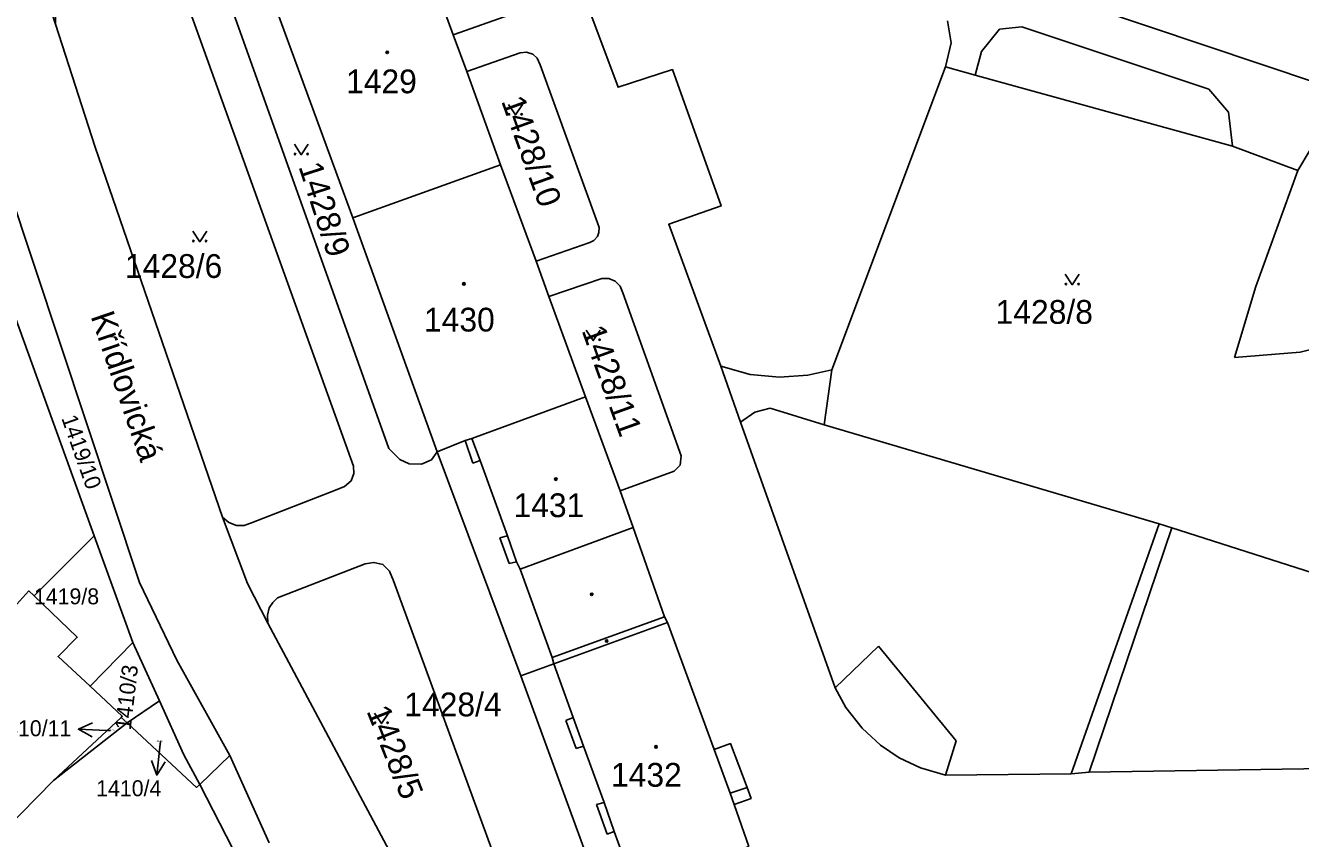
# Model space of a CAD drawing. Extents: x -598934 to -598196, y -1162208 to -1161502.
# Drawn here: x -598686.2 to -598595, y -1161698.2 to -1161640.1 of the extents above; entities that cross this region are included whole.
import ezdxf

# ---------------------------------------------------------------- set-up
doc = ezdxf.new("R2010")
doc.units = 0
for name, color, linetype in [('KN_CAR_KR', 7, 'Continuous'), ('KN_KULTURY', 7, 'Continuous'), ('KN_PARC_CIS_POM', 7, 'Continuous'), ('KN_PARC_CIS_POZ', 7, 'Continuous'), ('KN_PARC_CIS_STAV', 7, 'Continuous'), ('KN_PARC_PLOCHA', 7, 'Continuous'), ('KN_ULICE', 7, 'Continuous'), ('PARC_C_SIPKA', 7, 'Continuous'), ('parcely_l', 7, 'Continuous')]:
    doc.layers.add(name, color=color, linetype=linetype)

msp = doc.modelspace()

# ---------------------------------------------------------------- linework, layer by layer
at = {"layer": 'KN_CAR_KR'}
for points in [[(-598609.95, -1161638.83), (-598593.83, -1161644.24)], [(-598620.01, -1161641.36), (-598620.28, -1161639.8)], [(-598614.96, -1161640.21), (-598616.57, -1161640.38)], [(-598614.96, -1161640.21), (-598601.59, -1161644.68)], [(-598617.85, -1161641.98), (-598616.57, -1161640.38)], [(-598620.01, -1161641.36), (-598620.42, -1161643.09)], [(-598617.85, -1161641.98), (-598618.3, -1161643.68)], [(-598628.55, -1161664.74), (-598620.42, -1161643.09)], [(-598620.42, -1161643.09), (-598618.3, -1161643.68)], [(-598618.3, -1161643.68), (-598599.9, -1161648.76)], [(-598601.59, -1161644.68), (-598600.19, -1161646.33)], [(-598599.9, -1161648.76), (-598600.19, -1161646.33)], [(-598599.9, -1161648.76), (-598595.24, -1161650.49)], [(-598595.24, -1161650.49), (-598594.36, -1161649.02)], [(-598598.24, -1161658.79), (-598595.24, -1161650.49)], [(-598599.77, -1161663.85), (-598598.24, -1161658.79)], [(-598587.65, -1161661.6), (-598595.08, -1161663.48)], [(-598595.08, -1161663.48), (-598599.77, -1161663.85)], [(-598636.49, -1161664.47), (-598634.38, -1161665.08)], [(-598630.27, -1161665.13), (-598628.55, -1161664.74)], [(-598629.1, -1161668.66), (-598628.55, -1161664.74)], [(-598634.38, -1161665.08), (-598632.3, -1161665.26)], [(-598632.3, -1161665.26), (-598630.27, -1161665.13)], [(-598632.96, -1161667.48), (-598634.05, -1161667.76)], [(-598629.1, -1161668.66), (-598632.96, -1161667.48)], [(-598634.05, -1161667.76), (-598635.07, -1161668.48)], [(-598605.16, -1161675.75), (-598629.1, -1161668.66)], [(-598654.21, -1161671.41), (-598654.77, -1161669.8)], [(-598653.69, -1161671.22), (-598654.29, -1161669.64)], [(-598653.69, -1161671.22), (-598654.21, -1161671.41)], [(-598651.74, -1161676.61), (-598653.69, -1161671.22)], [(-598605.16, -1161675.75), (-598611.45, -1161693.61)], [(-598604.25, -1161676.04), (-598605.16, -1161675.75)], [(-598652.27, -1161676.75), (-598651.74, -1161676.61)], [(-598651.74, -1161676.61), (-598651.1, -1161678.47)], [(-598650.83, -1161678.98), (-598642.76, -1161676.01)], [(-598604.25, -1161676.04), (-598610.15, -1161693.51)], [(-598579.9, -1161683.83), (-598604.25, -1161676.04)], [(-598651.62, -1161678.59), (-598652.27, -1161676.75)], [(-598651.1, -1161678.47), (-598651.62, -1161678.59)], [(-598650.83, -1161678.98), (-598651.1, -1161678.47)], [(-598648.55, -1161685.29), (-598650.83, -1161678.98)], [(-598640.5, -1161682.4), (-598648.55, -1161685.29)], [(-598628.32, -1161687.47), (-598625.22, -1161684.5)], [(-598625.22, -1161684.5), (-598619.67, -1161691.25)], [(-598648.42, -1161685.75), (-598648.55, -1161685.29)], [(-598647.03, -1161689.59), (-598648.42, -1161685.75)], [(-598647.57, -1161689.8), (-598647.03, -1161689.59)], [(-598646.83, -1161691.81), (-598647.57, -1161689.8)], [(-598646.31, -1161691.64), (-598647.03, -1161689.59)], [(-598619.67, -1161691.25), (-598620.43, -1161693.71)], [(-598646.31, -1161691.64), (-598646.83, -1161691.81)], [(-598644.82, -1161695.66), (-598646.31, -1161691.64)], [(-598636.95, -1161691.89), (-598635.81, -1161695)], [(-598671.58, -1161692.3), (-598668.78, -1161698.56)], [(-598634.61, -1161694.6), (-598635.81, -1161695)], [(-598645.37, -1161695.82), (-598644.82, -1161695.66)], [(-598644.6, -1161697.92), (-598645.37, -1161695.82)], [(-598644.1, -1161697.73), (-598644.82, -1161695.66)], [(-598635.81, -1161695), (-598635.53, -1161695.8)], [(-598644.1, -1161697.73), (-598644.6, -1161697.92)], [(-598642.64, -1161701.79), (-598644.1, -1161697.73)]]:
    msp.add_lwpolyline(points, dxfattribs=at)
at = {"layer": 'KN_KULTURY'}
for points in [[(-598651.672, -1161645.772), (-598651.172, -1161646.522), (-598650.672, -1161645.772)], [(-598666.972, -1161648.612), (-598666.472, -1161649.362), (-598665.972, -1161648.612)], [(-598674.232, -1161654.832), (-598673.732, -1161655.582), (-598673.232, -1161654.832)], [(-598611.862, -1161657.912), (-598611.362, -1161658.662), (-598610.862, -1161657.912)], [(-598646.102, -1161661.892), (-598645.602, -1161662.642), (-598645.102, -1161661.892)], [(-598661.252, -1161689.272), (-598660.752, -1161690.022), (-598660.252, -1161689.272)]]:
    msp.add_lwpolyline(points, dxfattribs=at)
for centre, radius in [((-598660.33, -1161642.04), 0.09), ((-598660.33, -1161642.04), 0.0398), ((-598651.622, -1161646.471), 0.05), ((-598650.723, -1161646.471), 0.05), ((-598666.922, -1161649.311), 0.05), ((-598666.023, -1161649.311), 0.05), ((-598674.182, -1161655.531), 0.05), ((-598673.283, -1161655.531), 0.05), ((-598654.85, -1161658.59), 0.09), ((-598654.85, -1161658.59), 0.0398), ((-598611.812, -1161658.611), 0.05), ((-598610.913, -1161658.611), 0.05), ((-598646.052, -1161662.591), 0.05), ((-598645.153, -1161662.591), 0.05), ((-598648.28, -1161672.55), 0.09), ((-598648.28, -1161672.55), 0.0398), ((-598645.71, -1161680.79), 0.09), ((-598645.71, -1161680.79), 0.0398), ((-598644.64, -1161684.12), 0.09), ((-598644.64, -1161684.12), 0.0398), ((-598661.202, -1161689.971), 0.05), ((-598660.303, -1161689.971), 0.05), ((-598641.12, -1161691.69), 0.09), ((-598641.12, -1161691.69), 0.0398)]:
    msp.add_circle(centre, radius, dxfattribs=at)
at = {"layer": 'KN_PARC_PLOCHA'}
for points in [[(-598686.46, -1161632.58), (-598684.05, -1161640.04), (-598681.2, -1161648.82), (-598672.1, -1161675.27), (-598670.33, -1161680.01), (-598668.86, -1161682.84), (-598656.62, -1161705.79), (-598649.12, -1161714.49), (-598643.96, -1161720.2), (-598630.79, -1161735.6), (-598615.08, -1161754.64), (-598621.01, -1161760.25)], [(-598648.15, -1161632.92), (-598643.83, -1161644.54), (-598639.95, -1161643.28), (-598636.46, -1161653.02), (-598640.21, -1161654.33), (-598636.49, -1161664.47), (-598635.07, -1161668.48), (-598628.32, -1161687.47), (-598627.54, -1161688.87), (-598626.39, -1161690.35), (-598625.07, -1161691.56), (-598623.73, -1161692.47), (-598622.2, -1161693.2), (-598620.43, -1161693.71), (-598611.45, -1161693.61), (-598610.15, -1161693.51), (-598593.28, -1161693.23)], [(-598593.28, -1161693.23), (-598610.15, -1161693.51), (-598611.45, -1161693.61), (-598620.43, -1161693.71), (-598622.2, -1161693.2), (-598623.73, -1161692.47), (-598625.07, -1161691.56), (-598626.39, -1161690.35), (-598627.54, -1161688.87), (-598628.32, -1161687.47), (-598635.07, -1161668.48), (-598636.49, -1161664.47), (-598640.21, -1161654.33), (-598636.46, -1161653.02), (-598639.95, -1161643.28), (-598643.83, -1161644.54), (-598648.15, -1161632.92)], [(-598651.9, -1161639.47), (-598655.61, -1161640.79), (-598658.24, -1161633.59)], [(-598648.85, -1161709.97), (-598659.88, -1161679.81), (-598660.16, -1161679.12), (-598660.64, -1161678.65), (-598661.28, -1161678.5), (-598661.92, -1161678.6), (-598668.17, -1161681.04), (-598668.52, -1161681.36), (-598668.76, -1161681.75), (-598668.89, -1161682.28), (-598668.86, -1161682.84), (-598670.33, -1161680.01), (-598672.1, -1161675.27), (-598671.66, -1161675.65), (-598671.11, -1161675.86), (-598670.57, -1161675.86), (-598670.03, -1161675.68), (-598664.03, -1161673.35), (-598663.39, -1161673.09), (-598662.9, -1161672.67), (-598662.72, -1161672.16), (-598662.74, -1161671.63), (-598675.31, -1161636.67)], [(-598668.84, -1161637.36), (-598662.79, -1161653.87), (-598656.76, -1161670.59), (-598657.17, -1161671.17), (-598657.87, -1161671.49), (-598658.76, -1161671.46), (-598659.44, -1161671.16), (-598660.21, -1161670.37), (-598671.33, -1161639.25)], [(-598671.33, -1161639.25), (-598660.21, -1161670.37), (-598659.44, -1161671.16), (-598658.76, -1161671.46), (-598657.87, -1161671.49), (-598657.17, -1161671.17), (-598656.76, -1161670.59), (-598650.79, -1161686.62), (-598644.94, -1161702.57)], [(-598634.49, -1161698.82), (-598635.53, -1161695.8), (-598634.32, -1161695.37), (-598634.61, -1161694.6), (-598635.8, -1161691.46), (-598636.95, -1161691.89), (-598640.3, -1161682.8), (-598640.5, -1161682.4), (-598642.76, -1161676.01), (-598643.67, -1161673.38), (-598639.82, -1161671.99), (-598639.4, -1161671.56), (-598639.31, -1161670.88), (-598643.5, -1161659.24), (-598643.69, -1161658.75), (-598644.03, -1161658.39), (-598644.48, -1161658.21), (-598644.99, -1161658.22), (-598648.77, -1161659.49), (-598649.69, -1161656.97), (-598645.84, -1161655.64), (-598645.56, -1161655.49), (-598645.31, -1161655.21), (-598645.2, -1161654.92), (-598645.19, -1161654.57), (-598645.3, -1161654.24), (-598649.4, -1161642.93), (-598649.61, -1161642.46), (-598649.92, -1161642.17), (-598650.37, -1161642.03), (-598650.84, -1161642.09), (-598654.65, -1161643.41), (-598655.61, -1161640.79), (-598651.9, -1161639.47)], [(-598623.69, -1161762.79), (-598630.21, -1161755.2), (-598643.12, -1161738.93), (-598643.44, -1161738.54), (-598646.87, -1161734.51), (-598646.1, -1161732.88), (-598663.98, -1161712.27), (-598668.05, -1161705.44), (-598673.72, -1161694.38), (-598671.58, -1161692.3), (-598675.38, -1161685.5), (-598678.03, -1161679.94), (-598687.48, -1161651.51)], [(-598687.25, -1161681.97), (-598685.95, -1161680.54), (-598685.58, -1161680.89), (-598682.49, -1161683.85), (-598683.86, -1161685.23), (-598681.57, -1161687.36), (-598679.27, -1161689.5), (-598679.36, -1161689.58), (-598684.2, -1161694.1), (-598703.13, -1161713.4)], [(-598703.13, -1161713.4), (-598684.2, -1161694.1), (-598678.92, -1161689.98), (-598673.96, -1161694.59), (-598673.72, -1161694.38), (-598668.05, -1161705.44), (-598663.98, -1161712.27), (-598661.59, -1161716.28), (-598659.05, -1161719.64), (-598655.51, -1161724.33), (-598649.66, -1161731.23), (-598647.28, -1161734.03), (-598646.87, -1161734.51), (-598643.44, -1161738.54), (-598643.12, -1161738.93), (-598630.21, -1161755.2), (-598631.23, -1161754.62), (-598632.35, -1161754.49), (-598633.32, -1161754.79), (-598634.09, -1161755.38), (-598639.5, -1161760.37)]]:
    msp.add_lwpolyline(points, dxfattribs=at)
for points in [[(-598655.61, -1161640.79), (-598654.65, -1161643.41), (-598652.24, -1161650.08), (-598662.79, -1161653.87), (-598668.84, -1161637.36), (-598658.24, -1161633.59)], [(-598672.1, -1161675.27), (-598681.2, -1161648.82), (-598684.05, -1161640.04), (-598684.05, -1161639.16), (-598683.81, -1161638.35), (-598683.25, -1161637.58), (-598682.43, -1161637.05), (-598677.11, -1161635.02), (-598676.56, -1161635.06), (-598676.08, -1161635.26), (-598675.59, -1161635.87), (-598675.31, -1161636.67), (-598662.74, -1161671.63), (-598662.72, -1161672.16), (-598662.9, -1161672.67), (-598663.39, -1161673.09), (-598664.03, -1161673.35), (-598670.03, -1161675.68), (-598670.57, -1161675.86), (-598671.11, -1161675.86), (-598671.66, -1161675.65)], [(-598649.69, -1161656.97), (-598652.24, -1161650.08), (-598654.65, -1161643.41), (-598650.84, -1161642.09), (-598650.37, -1161642.03), (-598649.92, -1161642.17), (-598649.61, -1161642.46), (-598649.4, -1161642.93), (-598645.3, -1161654.24), (-598645.19, -1161654.57), (-598645.2, -1161654.92), (-598645.31, -1161655.21), (-598645.56, -1161655.49), (-598645.84, -1161655.64)], [(-598649.69, -1161656.97), (-598648.77, -1161659.49), (-598646.16, -1161666.68), (-598654.29, -1161669.64), (-598654.77, -1161669.8), (-598656.76, -1161670.59), (-598662.79, -1161653.87), (-598652.24, -1161650.08)], [(-598681.27, -1161676.6), (-598685.58, -1161680.89), (-598685.95, -1161680.54), (-598687.25, -1161681.97), (-598689.63, -1161679.64), (-598687.53, -1161677.48), (-598692.75, -1161672.48), (-598690.15, -1161669.88), (-598695.26, -1161664.81), (-598692.73, -1161662.19), (-598698.04, -1161657.01), (-598693.48, -1161653.2), (-598691.2, -1161650.93), (-598690.66, -1161650.66), (-598690.42, -1161651.33)], [(-598673.72, -1161694.38), (-598674.87, -1161692.27), (-598676.62, -1161688.4), (-598678.51, -1161684.23), (-598681.27, -1161676.6), (-598690.42, -1161651.33), (-598690.66, -1161650.66), (-598690.08, -1161650.46), (-598689.38, -1161650.41), (-598688.63, -1161650.59), (-598687.98, -1161650.98), (-598687.48, -1161651.51), (-598678.03, -1161679.94), (-598675.38, -1161685.5), (-598671.58, -1161692.3)], [(-598643.67, -1161673.38), (-598646.16, -1161666.68), (-598648.77, -1161659.49), (-598644.99, -1161658.22), (-598644.48, -1161658.21), (-598644.03, -1161658.39), (-598643.69, -1161658.75), (-598643.5, -1161659.24), (-598639.31, -1161670.88), (-598639.4, -1161671.56), (-598639.82, -1161671.99)], [(-598643.67, -1161673.38), (-598642.76, -1161676.01), (-598640.5, -1161682.4), (-598640.3, -1161682.8), (-598648.42, -1161685.75), (-598650.79, -1161686.62), (-598656.76, -1161670.59), (-598654.77, -1161669.8), (-598654.29, -1161669.64), (-598646.16, -1161666.68)], [(-598678.51, -1161684.23), (-598681.57, -1161687.36), (-598683.86, -1161685.23), (-598682.49, -1161683.85), (-598685.58, -1161680.89), (-598681.27, -1161676.6)], [(-598649.12, -1161714.49), (-598656.62, -1161705.79), (-598668.86, -1161682.84), (-598668.89, -1161682.28), (-598668.76, -1161681.75), (-598668.52, -1161681.36), (-598668.17, -1161681.04), (-598661.92, -1161678.6), (-598661.28, -1161678.5), (-598660.64, -1161678.65), (-598660.16, -1161679.12), (-598659.88, -1161679.81), (-598648.85, -1161709.97), (-598647.75, -1161713.25)], [(-598634.49, -1161698.82), (-598642.64, -1161701.79), (-598644.94, -1161702.57), (-598650.79, -1161686.62), (-598648.42, -1161685.75), (-598640.3, -1161682.8), (-598636.95, -1161691.89), (-598635.8, -1161691.46), (-598634.61, -1161694.6), (-598634.32, -1161695.37), (-598635.53, -1161695.8)], [(-598676.62, -1161688.4), (-598678.92, -1161689.98), (-598679.36, -1161689.58), (-598679.27, -1161689.5), (-598681.57, -1161687.36), (-598678.51, -1161684.23)], [(-598673.72, -1161694.38), (-598673.96, -1161694.59), (-598678.92, -1161689.98), (-598676.62, -1161688.4), (-598674.87, -1161692.27)], [(-598678.92, -1161689.98), (-598684.2, -1161694.1), (-598679.36, -1161689.58)]]:
    msp.add_lwpolyline(points, close=True, dxfattribs=at)
at = {"layer": 'PARC_C_SIPKA'}
for points in [[(-598681.428, -1161690.973), (-598682.409, -1161690.436), (-598681.391, -1161689.973)], [(-598680.12, -1161690.52), (-598680.4, -1161690.51), (-598682.409, -1161690.436)], [(-598676.53, -1161691.31), (-598676.58, -1161691.71), (-598676.808, -1161693.707)], [(-598676.198, -1161692.77), (-598676.808, -1161693.707), (-598677.191, -1161692.657)]]:
    msp.add_lwpolyline(points, dxfattribs=at)
at = {"layer": 'parcely_l'}
for points in [[(-598656.76, -1161670.59), (-598657.17, -1161671.17), (-598657.87, -1161671.49), (-598658.76, -1161671.46), (-598659.44, -1161671.16), (-598660.21, -1161670.37), (-598671.33, -1161639.25), (-598672.4, -1161636.02), (-598672.19, -1161635.03), (-598671.8, -1161634.41), (-598671.22, -1161633.94), (-598663.77, -1161631.3), (-598661.92, -1161630.82), (-598660.03, -1161630.71), (-598658.06, -1161631), (-598656.16, -1161631.68), (-598653.82, -1161633.91), (-598651.31, -1161637.82), (-598651.19, -1161638.33), (-598651.3, -1161638.86), (-598651.55, -1161639.21), (-598651.9, -1161639.47), (-598655.61, -1161640.79)], [(-598593.28, -1161693.23), (-598610.15, -1161693.51), (-598611.45, -1161693.61), (-598620.43, -1161693.71), (-598622.2, -1161693.2), (-598623.73, -1161692.47), (-598625.07, -1161691.56), (-598626.39, -1161690.35), (-598627.54, -1161688.87), (-598628.32, -1161687.47), (-598635.07, -1161668.48), (-598636.49, -1161664.47), (-598640.21, -1161654.33), (-598636.46, -1161653.02), (-598639.95, -1161643.28), (-598643.83, -1161644.54), (-598648.15, -1161632.92)], [(-598655.61, -1161640.79), (-598658.24, -1161633.59), (-598668.84, -1161637.36), (-598662.79, -1161653.87)], [(-598684.05, -1161640.04), (-598684.05, -1161639.16), (-598683.81, -1161638.35), (-598683.25, -1161637.58), (-598682.43, -1161637.05), (-598677.11, -1161635.02), (-598676.56, -1161635.06), (-598676.08, -1161635.26), (-598675.59, -1161635.87), (-598675.31, -1161636.67), (-598662.74, -1161671.63), (-598662.72, -1161672.16), (-598662.9, -1161672.67), (-598663.39, -1161673.09), (-598664.03, -1161673.35), (-598670.03, -1161675.68), (-598670.57, -1161675.86), (-598671.11, -1161675.86), (-598671.66, -1161675.65), (-598672.1, -1161675.27)], [(-598684.05, -1161640.04), (-598681.2, -1161648.82), (-598672.1, -1161675.27)], [(-598654.65, -1161643.41), (-598655.61, -1161640.79)], [(-598654.65, -1161643.41), (-598650.84, -1161642.09), (-598650.37, -1161642.03), (-598649.92, -1161642.17), (-598649.61, -1161642.46), (-598649.4, -1161642.93), (-598645.3, -1161654.24), (-598645.19, -1161654.57), (-598645.2, -1161654.92), (-598645.31, -1161655.21), (-598645.56, -1161655.49), (-598645.84, -1161655.64), (-598649.69, -1161656.97)], [(-598652.24, -1161650.08), (-598654.65, -1161643.41)], [(-598652.24, -1161650.08), (-598662.79, -1161653.87)], [(-598649.69, -1161656.97), (-598652.24, -1161650.08)], [(-598673.72, -1161694.38), (-598671.58, -1161692.3), (-598675.38, -1161685.5), (-598678.03, -1161679.94), (-598687.48, -1161651.51), (-598687.98, -1161650.98), (-598688.63, -1161650.59), (-598689.38, -1161650.41), (-598690.08, -1161650.46), (-598690.66, -1161650.66)], [(-598690.66, -1161650.66), (-598690.42, -1161651.33), (-598681.27, -1161676.6)], [(-598662.79, -1161653.87), (-598656.76, -1161670.59)], [(-598685.58, -1161680.89), (-598685.95, -1161680.54), (-598687.25, -1161681.97), (-598689.63, -1161679.64), (-598687.53, -1161677.48), (-598692.75, -1161672.48), (-598690.15, -1161669.88), (-598695.26, -1161664.81), (-598692.73, -1161662.19), (-598698.04, -1161657.01)], [(-598648.77, -1161659.49), (-598649.69, -1161656.97)], [(-598648.77, -1161659.49), (-598644.99, -1161658.22), (-598644.48, -1161658.21), (-598644.03, -1161658.39), (-598643.69, -1161658.75), (-598643.5, -1161659.24), (-598639.31, -1161670.88), (-598639.4, -1161671.56), (-598639.82, -1161671.99), (-598643.67, -1161673.38)], [(-598646.16, -1161666.68), (-598648.77, -1161659.49)], [(-598656.76, -1161670.59), (-598654.77, -1161669.8), (-598654.29, -1161669.64), (-598646.16, -1161666.68)], [(-598643.67, -1161673.38), (-598646.16, -1161666.68)], [(-598656.76, -1161670.59), (-598650.79, -1161686.62)], [(-598640.3, -1161682.8), (-598640.5, -1161682.4), (-598642.76, -1161676.01), (-598643.67, -1161673.38)], [(-598672.1, -1161675.27), (-598670.33, -1161680.01), (-598668.86, -1161682.84)], [(-598681.27, -1161676.6), (-598685.58, -1161680.89)], [(-598678.51, -1161684.23), (-598681.27, -1161676.6)], [(-598668.86, -1161682.84), (-598668.89, -1161682.28), (-598668.76, -1161681.75), (-598668.52, -1161681.36), (-598668.17, -1161681.04), (-598661.92, -1161678.6), (-598661.28, -1161678.5), (-598660.64, -1161678.65), (-598660.16, -1161679.12), (-598659.88, -1161679.81), (-598648.85, -1161709.97), (-598647.75, -1161713.25), (-598649.12, -1161714.49)], [(-598685.58, -1161680.89), (-598682.49, -1161683.85), (-598683.86, -1161685.23), (-598681.57, -1161687.36)], [(-598649.12, -1161714.49), (-598656.62, -1161705.79), (-598668.86, -1161682.84)], [(-598650.79, -1161686.62), (-598648.42, -1161685.75), (-598640.3, -1161682.8)], [(-598640.3, -1161682.8), (-598636.95, -1161691.89), (-598635.8, -1161691.46), (-598634.61, -1161694.6), (-598634.32, -1161695.37), (-598635.53, -1161695.8), (-598634.49, -1161698.82)], [(-598681.57, -1161687.36), (-598678.51, -1161684.23)], [(-598678.51, -1161684.23), (-598676.62, -1161688.4)], [(-598644.94, -1161702.57), (-598650.79, -1161686.62)], [(-598679.36, -1161689.58), (-598679.27, -1161689.5), (-598681.57, -1161687.36)], [(-598678.92, -1161689.98), (-598676.62, -1161688.4)], [(-598676.62, -1161688.4), (-598674.87, -1161692.27), (-598673.72, -1161694.38)], [(-598684.2, -1161694.1), (-598679.36, -1161689.58)], [(-598678.92, -1161689.98), (-598684.2, -1161694.1)], [(-598679.36, -1161689.58), (-598678.92, -1161689.98)], [(-598673.72, -1161694.38), (-598673.96, -1161694.59), (-598678.92, -1161689.98)], [(-598706.31, -1161710.25), (-598703.13, -1161713.4), (-598684.2, -1161694.1)], [(-598663.98, -1161712.27), (-598668.05, -1161705.44), (-598673.72, -1161694.38)]]:
    msp.add_lwpolyline(points, dxfattribs=at)

# ---------------------------------------------------------------- texts
at = {"layer": 'KN_PARC_CIS_POM'}
for s, p in [('1410/11', (-598680.278, -1161690.52)), ('1410/4', (-598676.813, -1161691.31))]:
    msp.add_text(s, height=0.1, dxfattribs=at).set_placement(p)
at = {"layer": 'KN_PARC_CIS_POZ'}
for s, height, rotation, p in [('1428/10', 1.7, 289.80022, (-598652.202, -1161645.518)), ('1428/9', 1.7, 288.0001, (-598666.69, -1161650.204)), ('1428/11', 1.7, 289.80022, (-598646.452, -1161661.918)), ('1419/10', 1.14, 289.5412, (-598683.641, -1161668.189)), ('1410/3', 1.14, 83.3945, (-598678.672, -1161690.529)), ('1428/5', 1.7, 291.59947, (-598661.834, -1161689.123))]:
    msp.add_text(s, height=height, rotation=rotation, dxfattribs=at).set_placement(p)
for s, height, p in [('1428/6', 1.7, (-598679.077, -1161658.17)), ('1428/8', 1.7, (-598616.837, -1161661.45)), ('1419/8', 1.14, (-598685.59, -1161681.5)), ('1428/4', 1.7, (-598659.107, -1161689.507)), ('1410/11', 1.14, (-598688.425, -1161690.93)), ('1410/4', 1.14, (-598681.14, -1161695.22))]:
    msp.add_text(s, height=height, dxfattribs=at).set_placement(p)
at = {"layer": 'KN_PARC_CIS_STAV'}
for s, p in [('1429', (-598663.272, -1161644.97)), ('1430', (-598657.702, -1161662)), ('1431', (-598651.302, -1161675.27)), ('1432', (-598644.332, -1161694.54))]:
    msp.add_text(s, height=1.7, dxfattribs=at).set_placement(p)
at = {"layer": 'KN_ULICE'}
msp.add_text('Křídlovická', height=1.7, rotation=288.89983, dxfattribs=at).set_placement((-598681.552, -1161660.905))

doc.saveas('drawing.dxf')
